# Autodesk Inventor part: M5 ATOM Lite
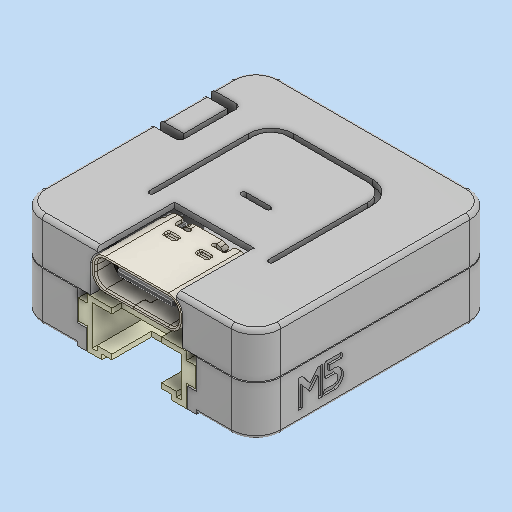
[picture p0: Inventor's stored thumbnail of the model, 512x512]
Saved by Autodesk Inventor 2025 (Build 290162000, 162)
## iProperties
Created: 2021-06
Part Number: M5 ATOM Lite
Material: Generico
Document SubType Name: Modeling
Designer: Ryzen5700u
Density: 1 g/cm^3
Appearance: Default
Author: Ryzen5700u
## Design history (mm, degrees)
feature "Solido1"
feature "Solido2:1"
feature "Solido3:1"
feature "Solido4:1"
feature "Solido5:1"
feature "Solido6:1"
feature "Solido7:1"
feature "Solido8:1"
feature "Solido9:1"
feature "Solido10:1"
feature "Solido11:1"
feature "Solido12:1"
feature "Solido13:1"
node "Solido2"
node "Solido3"
node "Solido4"
node "Solido5"
node "Solido6"
node "Solido7"
node "Solido8"
node "Solido9"
node "Solido10"
node "Solido11"
node "Solido12"
node "Solido13"
node "Solido14"
